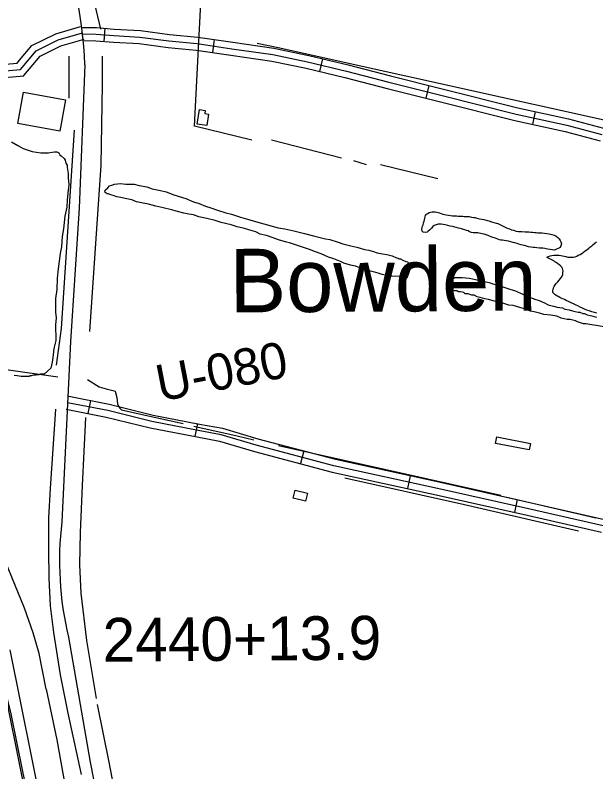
# Model space of a CAD drawing. Extents: x 3355724 to 3393621, y 594744 to 620174.
# Drawn here: x 3388099 to 3389424, y 603340 to 605066 of the extents above; entities that cross this region are included whole.
import ezdxf

# ---------------------------------------------------------------- set-up
doc = ezdxf.new("R2010")
doc.units = 0
for name, color, linetype in [('V-BLDG-OTLN', 7, 'Continuous'), ('V-FLOD-BASE', 7, 'Continuous'), ('V-LEVE-TOET', 7, 'Continuous'), ('V-RIVR-RANG-IDEN', 7, 'Continuous'), ('V-ROAD-CNTR', 7, 'Continuous'), ('V-SITE-OTLN', 7, 'Continuous'), ('V-SITE-VEGE', 7, 'Continuous'), ('V-SURV-IDEN', 7, 'Continuous'), ('V-SURV-LINE', 7, 'Continuous'), ('V-TOPO-GNAM-IDEN', 7, 'Continuous'), ('V-TOPO-SHOR', 7, 'Continuous')]:
    doc.layers.add(name, color=color, linetype=linetype)

msp = doc.modelspace()

# ---------------------------------------------------------------- linework, layer by layer
at = {"layer": 'V-BLDG-OTLN'}
for points in [[(3388514.3, 604817.3), (3388519.4, 604850.8), (3388532.6, 604848.8), (3388531.5, 604841.8), (3388540.1, 604840.5), (3388536, 604814)], [(3389198, 604103.7), (3389274.6, 604088.6), (3389271.7, 604074), (3389195.1, 604089.1)], [(3388737.5, 603982.6), (3388766.2, 603975.5), (3388761.6, 603957), (3388732.9, 603964.1)]]:
    msp.add_lwpolyline(points, close=True, dxfattribs=at)
at = {"layer": 'V-FLOD-BASE'}
msp.add_lwpolyline([(3388072.3, 603539.6), (3388088.5, 603472.3), (3388114.6, 603344), (3388142.1, 603212.2), (3388170.3, 603074.2), (3388177.4, 603034.7)], dxfattribs=at)
at = {"layer": 'V-LEVE-TOET'}
for points in [[(3388169.5, 603528.1), (3388153.2, 603609.8), (3388139.8, 603656.6), (3388119.9, 603713.4), (3388054.3, 603871.3), (3387987.4, 604041.6), (3387914.6, 604212.7), (3387854.9, 604371.8), (3387775.8, 604569.2), (3387694.6, 604755.5), (3387631.6, 604920.6), (3387627.8, 604935.1), (3387624, 604948.9), (3387618.2, 604960.8), (3387609, 604972.1), (3387596.7, 604990), (3387584.5, 605019), (3387554.8, 605083.8)], [(3388169.5, 603528.1), (3388193.5, 603412.3), (3388221.1, 603259.7)]]:
    msp.add_lwpolyline(points, dxfattribs=at)
at = {"layer": 'V-ROAD-CNTR'}
for p, q in [((3388303.7, 605036.1), (3388301.2, 605006.2)), ((3388553.2, 605010.4), (3388548.8, 604980.8)), ((3388800.4, 604966.7), (3388793.6, 604937.5)), ((3389043, 604905.8), (3389035.9, 604876.6)), ((3389285.4, 604846.2), (3389279, 604816.9)), ((3388270.3, 604186.8), (3388264.5, 604157.3)), ((3388514.6, 604134.2), (3388508.9, 604104.7)), ((3388757.6, 604071.8), (3388749.8, 604042.8)), ((3389000.3, 604015.3), (3388993.9, 603986)), ((3389244.5, 603961), (3389237.9, 603931.7))]:
    msp.add_line(p, q, dxfattribs=at)
for points in [[(3387543.7, 605427.6), (3387451.7, 605364.4), (3387443.2, 605349.6), (3387598.2, 605038.2), (3387613.1, 605009.2), (3387980, 604930.8), (3388111.1, 604942.3), (3388146.4, 604984.6), (3388197.2, 605009.8), (3388252.2, 605025.5)], [(3388109, 604963.2), (3388136.9, 604996.7), (3388191.7, 605023.8), (3388248.1, 605039.9)], [(3388252.7, 605038.2), (3388284.6, 605037.7), (3388325, 605034.2), (3388384.7, 605031.2), (3388451.1, 605022.1), (3388515.5, 605016), (3388595.6, 605004.1), (3388689.4, 604990.8), (3388769.1, 604974.1), (3388858.6, 604953), (3388955.4, 604927.4), (3389073.4, 604898.3), (3389245.6, 604854.9), (3389361.3, 604829.5), (3389441, 604808.1)], [(3388252.5, 605023.2), (3388283.8, 605022.7), (3388324, 605019.3), (3388383.3, 605016.2), (3388449.4, 605007.2), (3388513.7, 605001.1), (3388593.4, 604989.3), (3388686.8, 604976), (3388765.8, 604959.4), (3388854.9, 604938.5), (3388951.6, 604912.9), (3389069.8, 604883.7), (3389242.1, 604840.3), (3389357.8, 604815), (3389437.4, 604793.5)], [(3388118.9, 604928.3), (3388155.9, 604972.6), (3388202.6, 604995.7), (3388256.4, 605011.1)], [(3388252.3, 605008.2), (3388283.1, 605007.7), (3388322.9, 605004.3), (3388381.8, 605001.3), (3388447.6, 604992.3), (3388511.9, 604986.2), (3388591.2, 604974.4), (3388684.2, 604961.2), (3388762.5, 604944.8), (3388851.3, 604923.9), (3388947.9, 604898.4), (3389066.1, 604869.2), (3389238.7, 604825.7), (3389354.2, 604800.4), (3389433.7, 604779)], [(3387941, 604954.5), (3387981, 604946), (3388103.6, 604956.7), (3388109, 604963.2)], [(3388257.7, 604952.9), (3388244.5, 604625.7), (3388225, 604321.2), (3388205.4, 603910.1)], [(3387934.8, 604925.2), (3387979.1, 604915.7), (3388118.6, 604927.9), (3388118.9, 604928.3)], [(3388221.2, 604196.4), (3388313.2, 604178.4), (3388413.7, 604153.7), (3388519.4, 604133.2), (3388572.1, 604123.4), (3388652.8, 604099.7), (3388829.5, 604052.7), (3389065.7, 604001), (3389273.5, 603954.5), (3389443.5, 603915.7), (3389599.5, 603883.3), (3389691.4, 603866), (3389836.9, 603843.5), (3389986.9, 603808.5), (3390096.8, 603781.2), (3390210.5, 603750.3), (3390354.5, 603719.1), (3390541, 603675.9), (3390669.1, 603646.1), (3390747.7, 603626.3), (3390789.2, 603610.5), (3390799.6, 603604.6)], [(3388215.5, 604166.9), (3388306.7, 604149.1), (3388407.2, 604124.4), (3388513.8, 604103.7), (3388565.1, 604094.2), (3388644.7, 604070.8), (3388822.5, 604023.5), (3389059.2, 603971.7), (3389266.9, 603925.3), (3389437.1, 603886.4)], [(3389440.3, 603901), (3389270.2, 603939.9), (3389062.5, 603986.4), (3388826, 604038.1), (3388648.7, 604085.2), (3388568.6, 604108.8), (3388516.6, 604118.5), (3388410.4, 604139), (3388310, 604163.7), (3388218.3, 604181.6)], [(3388220.4, 603647.2), (3388270, 603361.8), (3388350.9, 602950), (3388437.8, 602503.3)]]:
    msp.add_lwpolyline(points, dxfattribs=at)
for centre, radius, start, end in [((3387337, 604920.6), 921.2, 2.0052, 22.8972), ((3388940.9, 603820.3), 741, 173.0346, 193.5077)]:
    msp.add_arc(centre, radius, start, end, dxfattribs=at)
at = {"layer": 'V-SITE-OTLN'}
msp.add_lwpolyline([(3388117.7, 604890.2), (3388213.6, 604872.9), (3388200.6, 604801.5), (3388104.7, 604818.8)], close=True, dxfattribs=at)
at = {"layer": 'V-SITE-VEGE'}
for points in [[(3388090.1, 604777.4), (3388105.1, 604769), (3388117.4, 604762), (3388137.9, 604755), (3388157.1, 604752.1), (3388174.9, 604751.9), (3388183.2, 604753.2), (3388188.7, 604754.5), (3388191.4, 604754.5), (3388194.2, 604754.5), (3388198.2, 604751.7), (3388201, 604747.5), (3388203.7, 604744.8), (3388210.5, 604739.2), (3388213.2, 604735.1), (3388214.5, 604728.2), (3388217.2, 604724.1), (3388217.2, 604718.6), (3388219.8, 604704.8), (3388219.7, 604695.2), (3388220.9, 604678.7), (3388219.4, 604666.4), (3388217.8, 604644.5), (3388216.3, 604628), (3388212, 604607.5), (3388209, 604578.7), (3388206.1, 604560.9), (3388204.5, 604537.6), (3388201.6, 604522.5), (3388197.2, 604486.9), (3388194.3, 604466.3), (3388194, 604440.2), (3388191.1, 604419.7), (3388190.8, 604388.1), (3388192.1, 604375.8), (3388190.5, 604359.3), (3388190.5, 604349.7), (3388191.7, 604334.6), (3388191.6, 604323.6), (3388187.3, 604305.8), (3388185.8, 604290.8), (3388184.4, 604285.3), (3388182.9, 604274.3), (3388180, 604260.6), (3388164.8, 604247), (3388160.7, 604247.1), (3388156.6, 604247.1), (3388152.5, 604245.8), (3388147, 604244.5), (3388140.1, 604244.5), (3388136, 604243.2), (3388133.2, 604243.2), (3388130.5, 604241.9), (3388112.6, 604242), (3388103, 604243.5), (3388096.2, 604243.6)], [(3388992.8, 604465.9), (3388984.6, 604467.3), (3388976.4, 604470.1), (3388958.6, 604470.3), (3388951.7, 604473.1), (3388943.5, 604473.2), (3388936.6, 604474.6), (3388927.1, 604477.4), (3388921.6, 604478.9), (3388909.3, 604481.7), (3388899.7, 604484.6), (3388875.1, 604493), (3388864.1, 604495.9), (3388849.1, 604500.1), (3388840.9, 604504.3), (3388825.8, 604509.9), (3388813.5, 604514.2), (3388797.1, 604521.2), (3388782.1, 604526.8), (3388772.5, 604531), (3388741, 604540.9), (3388724.6, 604546.5), (3388717.8, 604548), (3388700, 604553.6), (3388687.7, 604557.8), (3388672.6, 604563.5), (3388657.6, 604566.4), (3388648, 604571.9), (3388631.6, 604576.2), (3388622, 604579), (3388605.6, 604583.3), (3388591.9, 604587.5), (3388568.6, 604593.2), (3388555, 604597.5), (3388535.8, 604601.8), (3388518, 604606.1), (3388505.7, 604610.3), (3388494.7, 604611.8), (3388483.8, 604614.6), (3388466, 604618.9), (3388456.4, 604621.7), (3388442.7, 604624.6), (3388433.1, 604627.4), (3388419.4, 604630.3), (3388403, 604634.5), (3388390.7, 604637.4), (3388375.6, 604640.3), (3388364.7, 604644.5), (3388349.6, 604647.4), (3388340, 604650.2), (3388330.4, 604651.7), (3388322.2, 604654.5), (3388316.7, 604655.9), (3388311.3, 604658.7), (3388308.5, 604658.7), (3388304.4, 604661.5), (3388303.1, 604664.3), (3388304.5, 604667), (3388310, 604672.4), (3388314.2, 604676.5), (3388319.7, 604677.8), (3388325.2, 604680.5), (3388338.9, 604681.8), (3388351.3, 604680.3), (3388370.5, 604680.1), (3388381.4, 604677.3), (3388399.2, 604674.4), (3388411.6, 604670.1), (3388430.7, 604665.9), (3388443, 604663), (3388460.8, 604656), (3388488.2, 604647.5), (3388506, 604640.5), (3388518.3, 604636.2), (3388533.3, 604630.6), (3388545.6, 604626.4), (3388560.7, 604620.8), (3388579.8, 604615.1), (3388592.1, 604612.2), (3388612.7, 604605.2), (3388629.1, 604600.9), (3388652.3, 604593.8), (3388698.9, 604581.1), (3388713.9, 604578.2), (3388734.5, 604573.9), (3388759.1, 604568.2), (3388779.7, 604562.5), (3388792, 604559.6), (3388807, 604555.4), (3388816.6, 604553.9), (3388835.8, 604548.3), (3388846.7, 604544), (3388864.5, 604539.8), (3388878.2, 604536.9), (3388886.4, 604534.1), (3388896, 604531.2), (3388905.6, 604529.8), (3388916.5, 604526.9), (3388924.8, 604524.1), (3388937.1, 604521.3), (3388946.7, 604519.8)], [(3388946.7, 604519.8), (3388959, 604516.9), (3388968.6, 604512.7), (3388972.7, 604511.3), (3388975.4, 604509.9), (3388978.1, 604509.9), (3388983.6, 604507.1), (3388990.4, 604504.3), (3388994.5, 604502.9), (3388997.2, 604498.8), (3389000, 604496), (3389001.3, 604491.9), (3388992.8, 604465.9)], [(3389443.2, 604354.7), (3389400.8, 604362), (3389395.3, 604362), (3389381.6, 604366.3), (3389377.5, 604369), (3389365.2, 604371.9), (3389358.3, 604372), (3389344.6, 604374.8), (3389335.1, 604379), (3389321.4, 604381.9), (3389304.9, 604383.4), (3389295.3, 604386.3), (3389283, 604389.1), (3389274.8, 604390.6), (3389261.1, 604396.2), (3389250.2, 604399), (3389235.1, 604403.3), (3389225.5, 604404.7), (3389215.9, 604407.6), (3389202.3, 604411.8), (3389192.7, 604413.3), (3389179, 604417.5), (3389170.8, 604419), (3389159.8, 604421.8), (3389153, 604423.2), (3389146.1, 604427.4), (3389140.7, 604427.5), (3389132.5, 604430.3), (3389125.6, 604430.3), (3389122.9, 604433.1), (3389114.7, 604434.6), (3389110.5, 604434.6), (3389106.4, 604437.4), (3389102.3, 604437.4), (3389096.9, 604438.8), (3389092.8, 604441.6), (3389090, 604443), (3389087.3, 604444.4), (3389086, 604448.6), (3389087.4, 604451.3), (3389087.4, 604454), (3389090.2, 604456.7), (3389091.6, 604460.8), (3389099.9, 604466.3), (3389102.6, 604467.6), (3389119.1, 604467.5), (3389135.5, 604465.9), (3389149.2, 604463.1), (3389165.6, 604458.8), (3389180.7, 604455.9), (3389188.9, 604453.1), (3389205.3, 604448.8), (3389216.3, 604444.6), (3389230, 604440.4), (3389238.2, 604437.6), (3389251.8, 604431.9), (3389271, 604423.5), (3389284.6, 604417.9), (3389294.2, 604415.1), (3389306.5, 604409.5), (3389314.7, 604405.3), (3389327, 604402.4), (3389335.2, 604399.6), (3389347.6, 604398.1), (3389353, 604395.3), (3389362.6, 604393.9), (3389370.8, 604391.1), (3389376.3, 604389.6), (3389383.2, 604388.2), (3389387.3, 604388.2), (3389394.1, 604385.4), (3389398.2, 604385.3), (3389403.7, 604382.5), (3389410.5, 604381.1), (3389414.6, 604379.7), (3389425.6, 604376.8)]]:
    msp.add_lwpolyline(points, dxfattribs=at)
at = {"layer": 'V-SURV-LINE'}
for points in [[(3388086.3, 603617.7), (3388308.2, 602518.3)], [(3388278.8, 602512.3), (3388056.9, 603611.7)]]:
    msp.add_lwpolyline(points, dxfattribs=at)
at = {"layer": 'V-TOPO-SHOR'}
for p, q in [((3388221.2, 604972.5), (3388221.5, 604876.7)), ((3388843.2, 604740), (3388683.5, 604781)), ((3388900.7, 604724.2), (3388871.9, 604733.7)), ((3389063.5, 604692.7), (3388932.6, 604724.2))]:
    msp.add_line(p, q, dxfattribs=at)
for points in [[(3388293.9, 605034.1), (3388274.5, 605118.3), (3388232, 605233.2), (3388166.5, 605374.9), (3388097.2, 605482), (3388031.8, 605573.9), (3387931.9, 605677.1)], [(3388638.8, 604780.9), (3388507.9, 604812.5), (3388523.1, 605109.3)], [(3390148.5, 604670), (3388698.9, 604991.7), (3388651, 605001.1)], [(3388268.9, 604344), (3388294.7, 604723.6), (3388298.1, 604907.6), (3388297.9, 604972.7)], [(3388233.2, 604803.9), (3388203.7, 604351.5), (3388192.4, 604267.2)], [(3389329.2, 604530), (3389324.2, 604530.5), (3389319.6, 604531.4), (3389313.2, 604532.4), (3389307.7, 604533.6), (3389302.7, 604534.1), (3389298.1, 604534.6), (3389294.9, 604534.8), (3389289.2, 604535.1), (3389284.4, 604535.6), (3389281, 604535.9), (3389275.5, 604536.9), (3389270.5, 604537.8), (3389265.9, 604539), (3389261.1, 604540.2), (3389256.3, 604541.4), (3389253.4, 604542.3), (3389248.4, 604543.7), (3389244, 604544.9), (3389238.8, 604546.3), (3389235.4, 604547.1), (3389229.7, 604548.7), (3389224.4, 604550.1), (3389219.4, 604551.1), (3389214.4, 604552), (3389210.9, 604552.5), (3389206.8, 604552.8), (3389203.9, 604553.5), (3389200, 604554.9), (3389196.1, 604556.6), (3389192.5, 604557.7), (3389188.8, 604558.9), (3389185.2, 604560.5), (3389181.3, 604562), (3389177.9, 604563.4), (3389173.5, 604564.5), (3389168.8, 604566), (3389164.4, 604567.1), (3389161.2, 604567.9), (3389157.8, 604568.3), (3389154.6, 604569.1), (3389150.7, 604569.3), (3389147.5, 604569.4), (3389143.9, 604569.2), (3389140, 604570.3), (3389135.6, 604572), (3389132.2, 604573.6), (3389128.6, 604575), (3389125.2, 604576), (3389122.2, 604576.9), (3389117.2, 604578.3), (3389114.2, 604579), (3389110.3, 604580.2), (3389105.1, 604581.2), (3389099.4, 604582.8), (3389096.4, 604583.5), (3389091.6, 604584.7), (3389085.9, 604586.4), (3389080.2, 604587.6), (3389075.4, 604588.8), (3389071.1, 604589.3), (3389067.9, 604589.1), (3389063.8, 604588.9), (3389059.4, 604587.8), (3389055.1, 604586.2), (3389051.8, 604583.5), (3389048.6, 604580.3), (3389046.3, 604578.1), (3389044, 604575.3), (3389041.4, 604573.1), (3389038.7, 604571.3), (3389034.3, 604570.2), (3389030, 604571.1), (3389027.5, 604573.4), (3389027.1, 604577.1), (3389027.3, 604581.4), (3389028.5, 604584.6), (3389029.5, 604588), (3389030.4, 604591.9), (3389031.8, 604595.8), (3389032.8, 604599.4), (3389033.7, 604602.9), (3389034.2, 604605.8), (3389035.4, 604609), (3389037.7, 604611.7), (3389040.2, 604613.8), (3389043.4, 604615.6), (3389046.4, 604616.7), (3389050.3, 604617.6), (3389053.7, 604617.5), (3389057.2, 604617.3), (3389060.6, 604616.8), (3389064, 604615.9), (3389067.4, 604614.7), (3389071.1, 604613.5), (3389074.7, 604612.3), (3389078.6, 604611.4), (3389082.5, 604610.4), (3389087.3, 604609.5), (3389091.8, 604609), (3389096.6, 604608.5)], [(3389096.6, 604608.5), (3389101.2, 604608.4), (3389106, 604608.2), (3389109.4, 604607.7), (3389114.7, 604607.4), (3389120, 604607.1), (3389123.2, 604606.8), (3389128, 604606.6), (3389134.4, 604606.3), (3389140.1, 604605.3), (3389145.6, 604604.6), (3389148.5, 604604.1), (3389152.4, 604603.2), (3389158.3, 604601.7), (3389164, 604600.5), (3389167.9, 604599.6), (3389173.4, 604598.2), (3389179.3, 604596.5), (3389185.7, 604594.8), (3389191.4, 604593.2), (3389196.4, 604591.5), (3389200.1, 604590.4), (3389204.9, 604588.3), (3389209.6, 604586.4), (3389214.2, 604584.1), (3389218.5, 604581.7), (3389221.7, 604580.3), (3389227, 604578.2), (3389231.7, 604576.6), (3389235.6, 604575.2), (3389242.2, 604573.5), (3389247.7, 604572.8), (3389254.6, 604572.3), (3389262.6, 604572), (3389270.8, 604571.7), (3389275.8, 604571.1), (3389279.3, 604570.9), (3389284, 604570.2), (3389287.7, 604569.9), (3389291.1, 604569.6), (3389295.2, 604569.4), (3389301.6, 604569.1), (3389306.7, 604568.8), (3389311.9, 604568.1), (3389317.4, 604567.1), (3389323.1, 604565.5), (3389328.6, 604564.3), (3389333.1, 604561.9), (3389337, 604558.9), (3389340.2, 604555.7), (3389342.4, 604552), (3389344, 604548.6), (3389345.1, 604544.2), (3389343.7, 604539.7), (3389342.3, 604536.2), (3389329.2, 604530)], [(3389361.8, 604412.7), (3389356.1, 604415.2), (3389352.5, 604417.1), (3389348.8, 604418.7), (3389345, 604420.4), (3389341.5, 604422), (3389337.7, 604423.8), (3389334.5, 604425.5), (3389331.3, 604427.8), (3389328.4, 604430.1), (3389325.9, 604433.3), (3389325.7, 604437.4), (3389326.2, 604440.4), (3389327.1, 604443.8), (3389328.5, 604446.6), (3389330.8, 604450.4), (3389333.6, 604453.6), (3389337.1, 604457.7), (3389340.3, 604461.5), (3389343.1, 604465.2), (3389345.4, 604468.1), (3389347, 604470.9), (3389348.2, 604474.5), (3389348.7, 604478.2), (3389349.2, 604481.6), (3389348.7, 604485), (3389348.1, 604488), (3389346.3, 604491), (3389342.9, 604494.2), (3389339.5, 604496.8), (3389336.8, 604498.8), (3389333.1, 604501.6), (3389330.6, 604503.5), (3389327.9, 604505.3), (3389324.7, 604507), (3389318.6, 604510), (3389314.9, 604511.6), (3389312, 604513.9), (3389315.6, 604515.7), (3389319.3, 604516.6), (3389323.7, 604517.7), (3389328.5, 604518.4), (3389333.3, 604518.8), (3389337.2, 604518.7), (3389340.1, 604518.2), (3389343.6, 604517.5), (3389347.4, 604516.6), (3389351.8, 604515.9), (3389355, 604515.4), (3389360, 604514.2), (3389365, 604513.7), (3389368.7, 604513.6), (3389372.8, 604514.1), (3389376.5, 604514.9), (3389380.6, 604516.3), (3389383.8, 604518.1), (3389387.9, 604520.1), (3389391.8, 604522.6), (3389396, 604525.5), (3389399.2, 604528), (3389403.1, 604530.9), (3389407.5, 604534.1), (3389410, 604536.4), (3389414.4, 604540), (3389417.2, 604542), (3389421.6, 604545.9), (3389425.5, 604548.8)], [(3389426.3, 604386), (3389420.6, 604387.7), (3389414.6, 604389.5), (3389408.7, 604391.4), (3389403.2, 604393.3), (3389399.8, 604394.5), (3389394.8, 604396.8), (3389392.1, 604398.4), (3389388.2, 604400.1), (3389382.5, 604402.6), (3389379.1, 604404), (3389373, 604407.1), (3389367.5, 604409.9), (3389361.8, 604412.7)], [(3387967.5, 604297.3), (3388026.1, 604273.5), (3388073.1, 604258.7), (3388196.1, 604241.1)], [(3388263.8, 604234.4), (3388290.3, 604217.7), (3388306.7, 604213.5), (3388321.7, 604209.9), (3388327.1, 604207.8), (3388327.8, 604205.1), (3388330.4, 604193.4), (3388332.3, 604179), (3388334.4, 604174.2), (3388337.7, 604169.4), (3388341.1, 604165.9), (3388388.9, 604155.2), (3388482.4, 604134.6)], [(3388191, 604167), (3388178.7, 603986.3), (3388174.9, 603918.8), (3388175.2, 603844.7), (3388175.4, 603781.3), (3388178.9, 603718.6), (3388186.6, 603657.3), (3388201.7, 603560.9), (3388218.8, 603473.3), (3388249, 603333.9)], [(3388259.2, 604148.3), (3388251.5, 603993.3), (3388247, 603885.9), (3388245.2, 603811.6), (3388248.8, 603747.5), (3388261.6, 603639.5), (3388283.4, 603506.7)], [(3388506.3, 604128.2), (3388605.3, 604106.1), (3388643.5, 604097.5)], [(3388699.5, 604084), (3388849.7, 604050.5), (3389040.1, 604008.4), (3389206.7, 603970.6)], [(3388850.7, 604010.1), (3389124.4, 603949.5), (3389384.5, 603889.6)], [(3389221, 603966.4), (3389378, 603930), (3389423.7, 603919.4)], [(3388286.2, 603492.9), (3388312.7, 603361.5), (3388344.3, 603195), (3388379.9, 603025.7), (3388404.5, 602899.1)]]:
    msp.add_lwpolyline(points, dxfattribs=at)

# ---------------------------------------------------------------- texts
at = {"layer": 'V-RIVR-RANG-IDEN'}
msp.add_text('U-080', height=83, rotation=10.9443, dxfattribs=at).set_placement((3388429, 604184.1))
at = {"layer": 'V-SURV-IDEN'}
msp.add_text('2440+13.9', height=100, rotation=0.4766, dxfattribs=at).set_placement((3388298.7, 603590.6))
at = {"layer": 'V-TOPO-GNAM-IDEN'}
msp.add_text('Bowden', height=145, rotation=0.3574, dxfattribs=at).set_placement((3388588.2, 604387.7))

doc.saveas('drawing.dxf')
